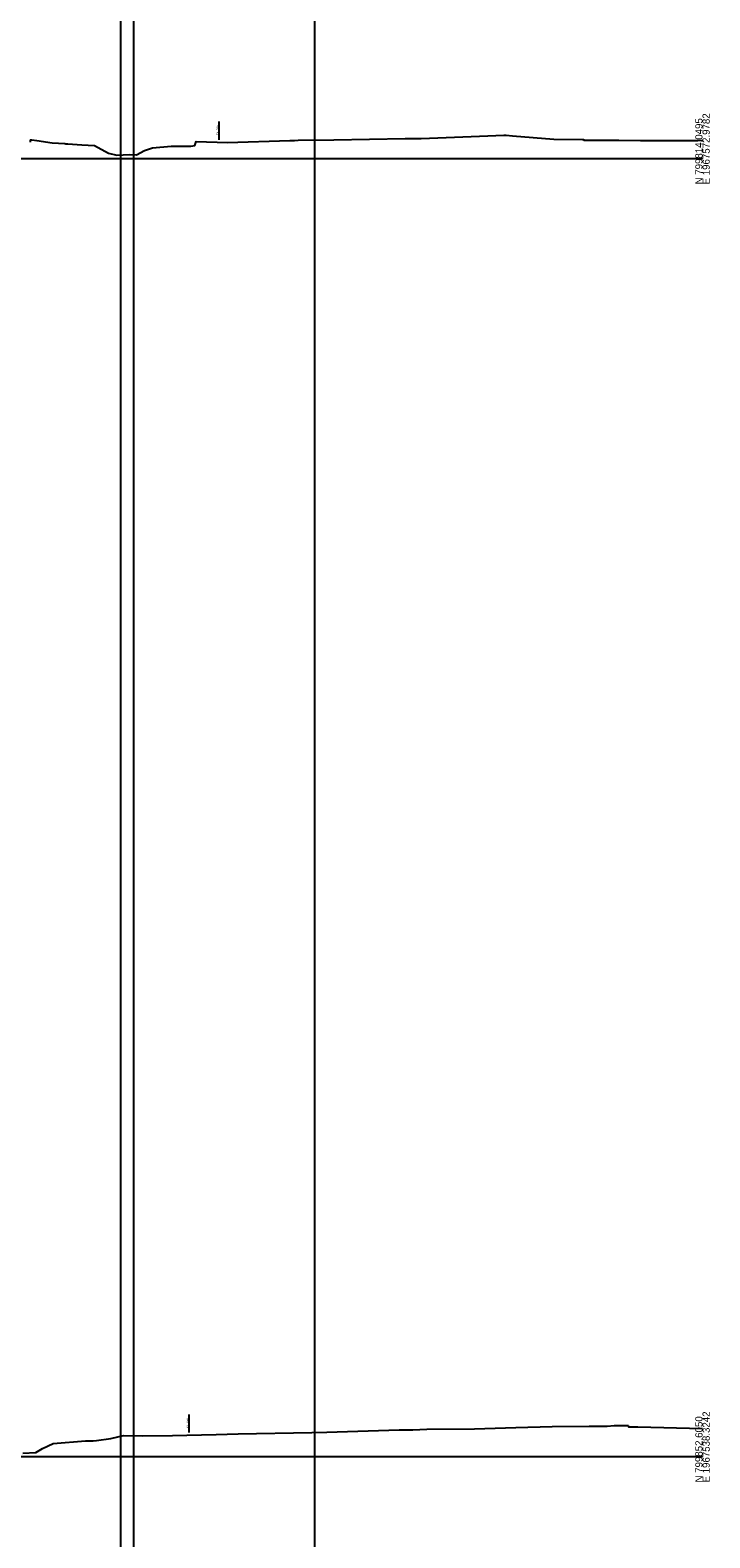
# Model space of a CAD drawing. Extents: x -119 to 6018, y -82 to 34226.
# Drawn here: x 340 to 603, y 30967 to 31550 of the extents above; entities that cross this region are included whole.
import ezdxf

# ---------------------------------------------------------------- set-up
doc = ezdxf.new("R2010")
doc.units = 0
for name, color, linetype in [('RD_GPK_XS_Cell', 7, 'Continuous'), ('RD_Sketch1', 7, 'Continuous'), ('RD_XS_ExGround', 7, 'Continuous'), ('RD_XS_ExPaveRet', 7, 'Continuous'), ('RD_XS_ExRW', 7, 'Continuous')]:
    doc.layers.add(name, color=color, linetype=linetype)

msp = doc.modelspace()

# ---------------------------------------------------------------- linework, layer by layer
at = {"layer": 'RD_GPK_XS_Cell'}
for p, q in [((300, 31500), (600, 31500)), ((300, 30998), (600, 30998))]:
    msp.add_line(p, q, dxfattribs=at)
at = {"layer": 'RD_Sketch1'}
for p, q in [((375, -82), (375, 34226.15)), ((380, -82), (380, 34226.15)), ((450, -82), (450, 34226.15))]:
    msp.add_line(p, q, dxfattribs=at)
at = {"layer": 'RD_XS_ExGround'}
for points in [[(339.91, 31507.29), (340.21, 31507.29), (340.54, 31507.29), (342.47, 31506.99), (348.42, 31506.11), (353.37, 31505.76), (353.67, 31505.74), (354.02, 31505.72), (354.53, 31505.68), (359.92, 31505.3), (364.82, 31505.03), (370.28, 31502.05), (373.44, 31501.3), (378.36, 31501.52), (381, 31501.47), (384.2, 31503.12), (387.24, 31504.13), (394.4, 31504.82), (395.73, 31504.81), (398.46, 31504.77), (402.04, 31504.73), (403.57, 31505.11), (404.07, 31506.58), (416.22, 31506.18), (440.39, 31507), (442.2, 31507.03), (443.65, 31507.06), (457.4, 31507.29), (484.95, 31507.7), (489.46, 31507.76), (491.23, 31507.78), (516.94, 31508.82), (523.14, 31509.04), (524.02, 31509.06), (526.55, 31508.84), (542.44, 31507.52), (553.63, 31507.42), (554.01, 31507.42), (554.14, 31507.17), (554.65, 31507.17), (567.63, 31507.07), (576.06, 31507.02), (579.23, 31506.99), (581.69, 31507.02), (595.18, 31506.99), (598.22, 31507.03), (600, 31507.07)], [(337.07, 30999.34), (342.16, 30999.55), (344.75, 31001.17), (348.81, 31003.09), (361.32, 31004.13), (363.79, 31004.12), (364.23, 31004.11), (365.53, 31004.27), (371.11, 31004.96), (376.05, 31006.2), (383.21, 31006.08), (395.04, 31006.2), (400.57, 31006.27), (411.85, 31006.61), (420.36, 31006.85), (448.92, 31007.38), (454.63, 31007.52), (482.64, 31008.32), (487.98, 31008.42), (493.32, 31008.57), (511.82, 31008.76), (527.83, 31009.28), (541.83, 31009.65), (556.12, 31009.76), (563.12, 31009.81), (565.84, 31009.98), (571.21, 31010), (571.34, 31009.55), (574.93, 31009.52), (600, 31008.85)]]:
    msp.add_lwpolyline(points, dxfattribs=at)
at = {"layer": 'RD_XS_ExPaveRet'}
msp.add_line((339.91, 31507.29), (339.91, 31506.29), dxfattribs=at)
at = {"layer": 'RD_XS_ExRW'}
for p, q in [((413.07, 31507.29), (413.07, 31514.29)), ((401.43, 31007.3), (401.43, 31014.3))]:
    msp.add_line(p, q, dxfattribs=at)

# ---------------------------------------------------------------- texts
at = {"layer": 'RD_GPK_XS_Cell'}
for s, p in [('N 799814.0495', (600, 31490)), ('E 1967572.9782', (602.8, 31490)), ('N 799852.6050', (600, 30988)), ('E 1967538.3242', (602.8, 30988))]:
    msp.add_text(s, height=2.8, rotation=90, dxfattribs=at).set_placement(p)
at = {"layer": 'RD_XS_ExRW'}
for p in [(412.81, 31508.96), (401.18, 31008.97)]:
    msp.add_text('EX. R/W ', height=0.75, rotation=90, dxfattribs=at).set_placement(p)

doc.saveas('drawing.dxf')
